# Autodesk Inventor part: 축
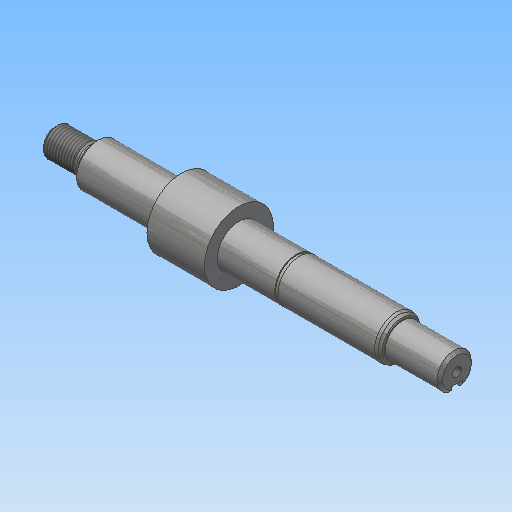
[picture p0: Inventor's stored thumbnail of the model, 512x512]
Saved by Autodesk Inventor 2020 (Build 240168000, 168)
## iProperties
Created: 2016-08
Part Number: 축
Material: 강철, 탄소
Document SubType Name: Modeling
Designer: mduedu
Density: 7.87 g/cm^3
Appearance: 강철
Author: mduedu
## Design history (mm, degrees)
sketch "스케치1"
  geometry: L1 (-70, 0)-(70, 0); L2 (-70, 0)-(-70, 5); L3 (-70, 5)-(-56, 5); L4 (-56, 5)-(-56, 7.5); L5 (-56, 7.5)-(49.355, 7.5); L6 (51, 7.5)-(51, 6.55); L7 (51, 6)-(70, 6); L8 (70, 6)-(70, 0); L9 (51, 6.55)-(49.355, 7.5); L10 (49.355, 7.5)-(51, 7.5); L11 (51, 6.55)-(51, 6); 2 further points
  constraints: 22 end point, 7 parallel, 2 perpendicular, 1 coincident, 1 horizontal, 1 midpoint
  dimensions: "d0" = 140 distance of L1.start L1.end; "d2" = 14 distance of L2.end L3.end; "d3" = 19 distance of L7.start L7.end; "d4" = 10 diameter of L3 L1; "d5" = 15 diameter of L5 L1; "d6" = 12 diameter of L7 L1; "d63" = 13.1 diameter of L6.end L1; "d64" = 30 deg angle of L5 L9
revolve "회전1" sketch "스케치1" stored, may be unused: angle "d7" = 90 deg
sketch "스케치2"
  geometry: L1 (-56, -5)-(-56, 5) reference; L2 (70, -6)-(70, 6) reference; L3 (-56, 0)-(70, 0); L4 (-58, 4.5)-(-58, 5); L5 (-58, 5)-(-56, 5); L6 (-56, 5)-(-56, 4.5); L7 (-58, 4.5)-(-56, 4.5); 1 further point
  constraints: 10 end point, 2 midpoint, 1 parallel, 1 perpendicular, 1 point on line
  dimensions: "d8" = 2 distance of L4.end L5.end; "d10" = 10 diameter of L5 L3; "d11" = 9 diameter of L7 L3
revolve "회전2" sketch "스케치2" stored, may be unused: angle "d12" = 90 deg
node "작업 평면1"
sketch "스케치3"
  geometry: C1 r 12 at (0, 0); 1 further point
  constraints: 1 centre point, 1 coincident
  dimensions: "d15" = 24 diameter of C1
extrude "돌출1" join sketch "스케치3" distance "d16" = 20; taper "d17" = 0 deg
sketch "스케치5"
  geometry: L1 (-70, -5)-(-70, 5) reference; L2 (70, -6)-(70, 6) reference; L3 (-70, 0)-(70, 0); L4 (-6, 7.5)-(49.355, 7.5) reference; L5 (15.15, 7.5)-(14, 7.5); L6 (14, 7.5)-(14, 7.15); L7 (14, 7.15)-(15.15, 7.15); L8 (15.15, 7.15)-(15.15, 7.5); 1 further point
  constraints: 10 end point, 2 midpoint, 2 parallel, 1 horizontal, 1 perpendicular, 1 point on line
  dimensions: "d19" = 56 distance between parallel lines of L6 L2; "d20" = 1.15 distance between parallel lines of L8 L6; "d21" = 14.3 diameter of L7 L3
revolve "회전3" sketch "스케치5" stored, may be unused: angle "d22" = 90 deg
node "작업 평면3"
sketch "스케치6"
  geometry: L1 (6.5, 2)-(-9.5, 2); L2 (-9.5, 2)-(-9.5, -2); L3 (-9.5, -2)-(6.5, -2); L4 (-9.5, 6)-(-9.5, -6) reference; A1 r 2 centre (6.5, 0) between (6.5, -2) and (6.5, 2); 2 further points
  constraints: 6 end point, 2 midpoint, 2 point on circle, 2 tangent, 1 centre point, 1 horizontal, 1 horizontal alignment, 1 parallel, 1 perpendicular
  dimensions: "d23" = 4 distance between parallel lines of L3 L1; "d62" = 18 dimension on A1 L2
extrude "돌출2" cut sketch "스케치6" distance "d25" = 2.5; taper "d26" = 0 deg
feature "스레드1" dims "d27" = 10, "d28" = 0
fillet "모깎기1" dims "d65" = 2
fillet "모깎기2" dims "d66" = 0.5
chamfer "모따기5" distance "d41" = 0.5; stored, may be unused: second distance "d42" = 2, angle "d43" = 45 deg
chamfer "모따기7" distance "d47" = 1; stored, may be unused: second distance "d48" = 2, angle "d49" = 45 deg
chamfer "모따기8" distance "d50" = 1; stored, may be unused: second distance "d51" = 2, angle "d52" = 45 deg
sketch "스케치8"
  geometry: 1 further point
hole "구멍1" sketch "스케치8" at (2, 3.5) diameter "d53" = 3.242; stored, may be unused: countersink angle "d57" = 90 deg, drill point angle "d59" = 120 deg; dims "d54" = 10, "d55" = 4, "d56" = 2, "d58" = 12
node "솔리드1"
other parameters: "d13" = -44
